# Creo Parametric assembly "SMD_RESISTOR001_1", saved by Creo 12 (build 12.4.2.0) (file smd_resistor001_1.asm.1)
Units: Custom; MM, KILOGRAM, SECS

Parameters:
  PTC_WM_ITERATION = "0"
  PTC_WM_VERSION = "-.0"
  PTC_WM_LIFECYCLE_STATE = "In Work"
  PTC_WM_LIFECYCLE = "MO_CADDocument"
  PTC_WM_CREATED_BY = "Maximilian Roepper (Z0017RMS: MO)"
  PTC_WM_CREATED_ON = "18-Sep-26 11:36:42 AM"
  PTC_WM_MODIFIED_BY = "Maximilian Roepper (Z0017RMS: MO)"
  PTC_WM_MODIFIED_ON = "18-Sep-26 11:36:46 AM"
  PDMLINKNUMBER = "PDM000071454845"
  PTC_WM_NUMBER = "PDM000071454845"

Other parameters: WEIGHT, WEIGHT_FACTOR, WEIGHT_ADD, MC_ERRORS, SUPPLIER

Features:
  1. coordinate system
  2. imported feature
  3. component "BODY_1"
  4. component "CONTACT1_1"
  5. component "CONTACT2_1"
  6. component "LABEL_1"
  7. component "PART010_1"

Other named items: DRW_VIEW_ORG, ROUGH-GROB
